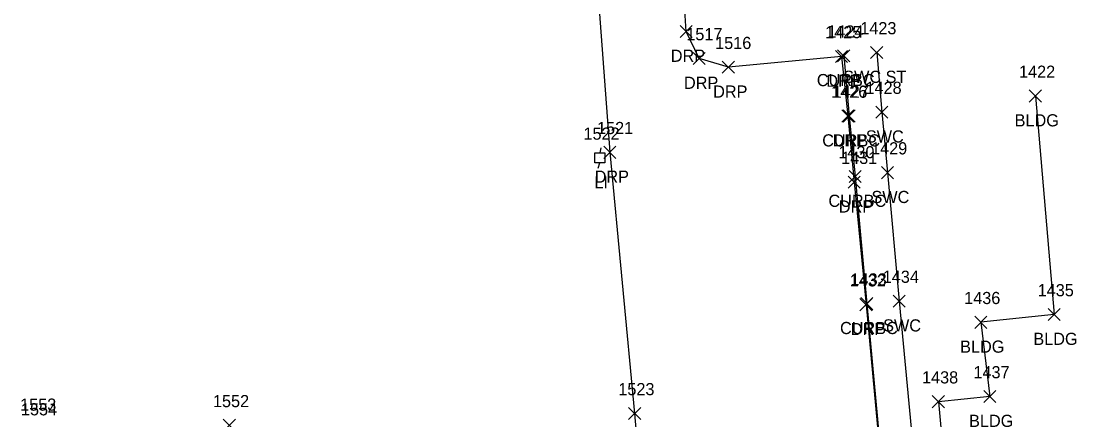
# Model space of a CAD drawing. Extents: x 1651305 to 1654558, y 539481 to 548441.
# Drawn here: x 1654378.2 to 1654554.1, y 544877.6 to 544943.1 of the extents above; entities that cross this region are included whole.
import ezdxf

# ---------------------------------------------------------------- set-up
doc = ezdxf.new("R2010")
doc.units = 0
for name, color, linetype in [('L_A', 7, 'Continuous'), ('L_I', 7, 'Continuous'), ('L_TIC', 7, 'Continuous'), ('LBC', 7, 'Continuous'), ('R_A', 7, 'Continuous'), ('R_I', 7, 'Continuous'), ('R_TIC', 7, 'Continuous'), ('RC', 7, 'Continuous'), ('RDP', 7, 'Continuous'), ('RSW', 7, 'Continuous'), ('U_A', 7, 'Continuous'), ('U_I', 7, 'Continuous'), ('ULP', 7, 'Continuous')]:
    doc.layers.add(name, color=color, linetype=linetype)

msp = doc.modelspace()

# ---------------------------------------------------------------- linework, layer by layer
at = {"layer": 'L_TIC'}
for points in [[(1654544.13, 544929.81), (1654546.13, 544931.81)], [(1654546.13, 544929.81), (1654544.13, 544931.81)], [(1654547.21, 544893.86), (1654549.21, 544895.86)], [(1654549.21, 544893.86), (1654547.21, 544895.86)], [(1654535.16, 544892.58), (1654537.16, 544894.58)], [(1654537.16, 544892.58), (1654535.16, 544894.58)], [(1654528.16, 544879.52), (1654530.16, 544881.52)], [(1654530.16, 544879.52), (1654528.16, 544881.52)], [(1654536.63, 544880.37), (1654538.63, 544882.37)], [(1654538.63, 544880.37), (1654536.63, 544882.37)], [(1654411.45, 544875.62), (1654413.45, 544877.62)], [(1654413.45, 544875.62), (1654411.45, 544877.62)]]:
    msp.add_lwpolyline(points, dxfattribs=at)
at = {"layer": 'LBC'}
msp.add_lwpolyline([(1654545.13, 544930.81), (1654548.21, 544894.86), (1654536.16, 544893.58), (1654537.63, 544881.37), (1654529.16, 544880.52), (1654531.23, 544858.19), (1654531.97, 544849.19), (1654552.51, 544851.02), (1654554.06, 544834.69)], dxfattribs=at)
at = {"layer": 'R_TIC'}
for points in [[(1654486.64, 544940.43), (1654488.64, 544942.43)], [(1654488.64, 544940.43), (1654486.64, 544942.43)], [(1654518.01, 544936.97), (1654520.01, 544938.97)], [(1654520.01, 544936.97), (1654518.01, 544938.97)], [(1654488.8, 544935.98), (1654490.8, 544937.98)], [(1654490.8, 544935.98), (1654488.8, 544937.98)], [(1654512.22, 544936.32), (1654514.22, 544938.32)], [(1654514.22, 544936.32), (1654512.22, 544938.32)], [(1654512.22, 544936.32), (1654514.22, 544938.32)], [(1654514.22, 544936.32), (1654512.22, 544938.32)], [(1654512.58, 544936.43), (1654514.58, 544938.43)], [(1654514.58, 544936.43), (1654512.58, 544938.43)], [(1654493.6, 544934.54), (1654495.6, 544936.54)], [(1654495.6, 544934.54), (1654493.6, 544936.54)], [(1654513.27, 544926.52), (1654515.27, 544928.52)], [(1654515.27, 544926.52), (1654513.27, 544928.52)], [(1654513.47, 544926.51), (1654515.47, 544928.51)], [(1654515.47, 544926.51), (1654513.47, 544928.51)], [(1654518.87, 544927.16), (1654520.87, 544929.16)], [(1654520.87, 544927.16), (1654518.87, 544929.16)], [(1654474.1, 544920.55), (1654476.1, 544922.55)], [(1654476.1, 544920.55), (1654474.1, 544922.55)], [(1654514.48, 544916.57), (1654516.48, 544918.57)], [(1654516.48, 544916.57), (1654514.48, 544918.57)], [(1654519.79, 544917.2), (1654521.79, 544919.2)], [(1654521.79, 544917.2), (1654519.79, 544919.2)], [(1654514.29, 544915.63), (1654516.29, 544917.63)], [(1654516.29, 544915.63), (1654514.29, 544917.63)], [(1654516.26, 544895.48), (1654518.26, 544897.48)], [(1654518.26, 544895.48), (1654516.26, 544897.48)], [(1654516.4, 544895.64), (1654518.4, 544897.64)], [(1654518.4, 544895.64), (1654516.4, 544897.64)], [(1654521.71, 544896.07), (1654523.71, 544898.07)], [(1654523.71, 544896.07), (1654521.71, 544898.07)], [(1654478.17, 544877.59), (1654480.17, 544879.59)], [(1654480.17, 544877.59), (1654478.17, 544879.59)]]:
    msp.add_lwpolyline(points, dxfattribs=at)
at = {"layer": 'RC'}
msp.add_lwpolyline([(1654513.58, 544937.43), (1654514.47, 544927.51), (1654515.48, 544917.57), (1654517.4, 544896.64), (1654520.05, 544868.14), (1654521.92, 544848.79), (1654524.02, 544826.91), (1654525.75, 544810.78), (1654514.75, 544809.77), (1654510.04, 544807.5)], dxfattribs=at)
at = {"layer": 'RDP'}
for points in [[(1654473.04, 544948.78), (1654475.1, 544921.55), (1654479.17, 544878.59), (1654482.23, 544843.6), (1654480.57, 544836.69), (1654476.02, 544831.84), (1654469.83, 544828.85), (1654462.34, 544827.89), (1654428.87, 544826.99), (1654415.21, 544824.36), (1654405.08, 544818.42), (1654397.43, 544809.88), (1654392.82, 544795.19), (1654389.4, 544756.56), (1654387.7, 544737.06)], [(1654513.22, 544937.32), (1654494.6, 544935.54), (1654489.8, 544936.98), (1654487.64, 544941.43), (1654487.13, 544949.4)], [(1654513.22, 544937.32), (1654514.27, 544927.52), (1654515.29, 544916.63), (1654517.26, 544896.48), (1654519.94, 544868.06), (1654521.75, 544848.74), (1654523.86, 544826.86), (1654525.5, 544810.78), (1654514.8, 544810.02), (1654509.87, 544807.54)]]:
    msp.add_lwpolyline(points, dxfattribs=at)
at = {"layer": 'RSW'}
msp.add_lwpolyline([(1654519.01, 544937.97), (1654519.87, 544928.16), (1654520.79, 544918.2), (1654522.71, 544897.07), (1654525.34, 544869.18), (1654526.55, 544857.81), (1654531.23, 544858.19)], dxfattribs=at)
at = {"layer": 'ULP'}
for p, q in [((1654472.61, 544919.79), (1654472.61, 544921.46)), ((1654472.61, 544921.46), (1654474.28, 544921.46)), ((1654473.61, 544922.29), (1654473.44, 544921.46)), ((1654474.28, 544921.46), (1654474.28, 544919.79)), ((1654474.28, 544919.79), (1654472.61, 544919.79)), ((1654473.19, 544918.96), (1654473.44, 544919.79)), ((1654473.44, 544920.62), (1654473.44, 544920.62))]:
    msp.add_line(p, q, dxfattribs=at)

# ---------------------------------------------------------------- texts
at = {"layer": 'L_A'}
for p in [(1654541.72, 544925.81), (1654544.8, 544889.86), (1654532.75, 544888.58), (1654534.22, 544876.37)]:
    msp.add_text('BLDG', height=2, dxfattribs=at).set_placement(p)
at = {"layer": 'L_I'}
for s, p in [('1422', (1654542.44, 544933.81)), ('1436', (1654533.41, 544896.58)), ('1435', (1654545.51, 544897.86)), ('1437', (1654534.94, 544884.37)), ('1438', (1654526.47, 544883.52)), ('1553', (1654378.02, 544879.04)), ('1553', (1654378.02, 544879.04)), ('1552', (1654409.76, 544879.62)), ('1554', (1654378.15, 544878.27)), ('1554', (1654378.15, 544878.27))]:
    msp.add_text(s, height=2, dxfattribs=at).set_placement(p)
at = {"layer": 'R_A'}
for s, p in [('DRP', (1654485.12, 544936.43)), ('DRP', (1654487.29, 544931.98)), ('CURBC', (1654509.16, 544932.43)), ('DRP', (1654510.71, 544932.32)), ('DRP', (1654510.71, 544932.32)), ('SWC ST', (1654513.5, 544932.97)), ('DRP', (1654492.09, 544930.54)), ('SWC', (1654517.23, 544923.16)), ('CURBC', (1654510.05, 544922.51)), ('DRP', (1654511.76, 544922.52)), ('DRP', (1654472.59, 544916.55)), ('CURBC', (1654511.07, 544912.57)), ('SWC', (1654518.15, 544913.2)), ('DRP', (1654512.78, 544911.63)), ('CURBC', (1654512.98, 544891.64)), ('DRP', (1654514.75, 544891.48)), ('SWC', (1654520.07, 544892.07))]:
    msp.add_text(s, height=2, dxfattribs=at).set_placement(p)
at = {"layer": 'R_I'}
for s, p in [('1424', (1654510.89, 544940.43)), ('1423', (1654516.31, 544940.97)), ('1517', (1654487.67, 544939.98)), ('1425', (1654510.53, 544940.32)), ('1425', (1654510.53, 544940.32)), ('1516', (1654492.42, 544938.54)), ('1426', (1654511.52, 544930.52)), ('1427', (1654511.77, 544930.51)), ('1428', (1654517.17, 544931.16)), ('1521', (1654472.98, 544924.55)), ('1429', (1654518.09, 544921.2)), ('1430', (1654512.7, 544920.57)), ('1431', (1654513.16, 544919.63)), ('1434', (1654520.01, 544900.07)), ('1432', (1654514.57, 544899.48)), ('1433', (1654514.71, 544899.64)), ('1523', (1654476.48, 544881.59))]:
    msp.add_text(s, height=2, dxfattribs=at).set_placement(p)
at = {"layer": 'U_A'}
msp.add_text('LI', height=2, dxfattribs=at).set_placement((1654472.54, 544915.62))
at = {"layer": 'U_I'}
msp.add_text('1522', height=2, dxfattribs=at).set_placement((1654470.75, 544923.62))

doc.saveas('drawing.dxf')
